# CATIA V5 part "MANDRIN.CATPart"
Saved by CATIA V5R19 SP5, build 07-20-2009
Part number: MANDRIN
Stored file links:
  C:\Users\Laurent\Desktop\Sujet Bac national\Sujet National E33\CFAO Catia\MANDRIN_TBI-2\MANDRIN.CATPart

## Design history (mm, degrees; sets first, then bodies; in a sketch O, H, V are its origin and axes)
Body1 (main body)
  Sketch1 on xy-plane, origin (0, 0, 0), H (1, 0, 0), V (0, 1, 0)
    circle A1 centre (0, 0) radius 105
    radius A1 = 105
  Pad1: profile Sketch1, direction (0, 0, 1), length 90
  Sketch2 on end face of Pad1, origin (0, 0, 90), H (1, 0, 0), V (0, 1, 0)
    circle A1 centre (0, 0) radius 30
    radius A1 = 30
  Pocket1: profile Sketch2, direction (0, 0, -1), through (limit type 3)
  Sketch3 on zx-plane, origin (0, 0, 0), H (-1, 0, 0), V (0, 0, 1)
    line L1 (-20, -2) -> (-20, 11)
    line L2 (-20, 11) -> (-32.5, 11)
    line L3 (-32.5, 11) -> (-32.5, 25)
    line L4 (-32.5, 25) -> (-20, 25)
    point P5 (-20, 25)
    line L5 (-20, 25) -> (-20, 38)
    line L6 (-20, 38) -> (20, 38)
    line L7 (20, 38) -> (20, 25)
    point P8 (20, 25)
    line L8 (20, 25) -> (32.5, 25)
    line L9 (32.5, 25) -> (32.5, 11)
    point P10 (32.5, 11)
    line L10 (32.5, 11) -> (20, 11)
    point P11 (20, 11)
    line L11 (20, 11) -> (20, -2)
    line L12 (20, -2) -> (-20, -2)
    reference projected line E1 (-105, 0) -> (105, 0) from edge [start face of Pad1 | face of Pad1 from Sketch1.A1]
    length L12 = 40
    distance L5 L3 = 12.5
    length L10 = 12.5
    distance L1 V = 20
    distance L6 L12 = 40
    length L1 = 13
    length L3 = 14
    distance L12 E1 = 2
    vertical: L1 V, L3 V, L5 V, L7 V, L9 V, L11 V
    horizontal: L2 H, L4 H, L6 H, L8 H, L10 H, L12 H
    coincidence: P5 L1, P8 L4, P10 L2, P11 L7
  Pocket2: profile Sketch3, direction (0, -1, 0), length 150
  CircPattern1: of Pocket2, instances 3, angular step 120, axis from face of Pad1 from Sketch1.A1
  Fillet1: radius 2, on edge [start face of Pad1 | face of Pad1 from Sketch1.A1] (x3)
  Chamfer1: length 1, angle 45, on edge [face of Pocket2 from Sketch3.L1 | start face of Pad1]; edge [face of CircPattern1 | start face of Pad1] (x2); edge [start face of Pad1 | face of CircPattern1] (x2); edge [start face of Pad1 | face of Pocket2 from Sketch3.L11]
